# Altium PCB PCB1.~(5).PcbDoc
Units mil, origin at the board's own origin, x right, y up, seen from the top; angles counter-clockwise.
Board outline 1968 x 1968 mil, 4 copper layers (Top Layer, Internal Plane 1, Internal Plane 2, Bottom Layer), stack 18.2 mil thick; 12 components, 11 nets, 37 pads, 0 vias.
Unrouted connection lines stored in the file: 1.
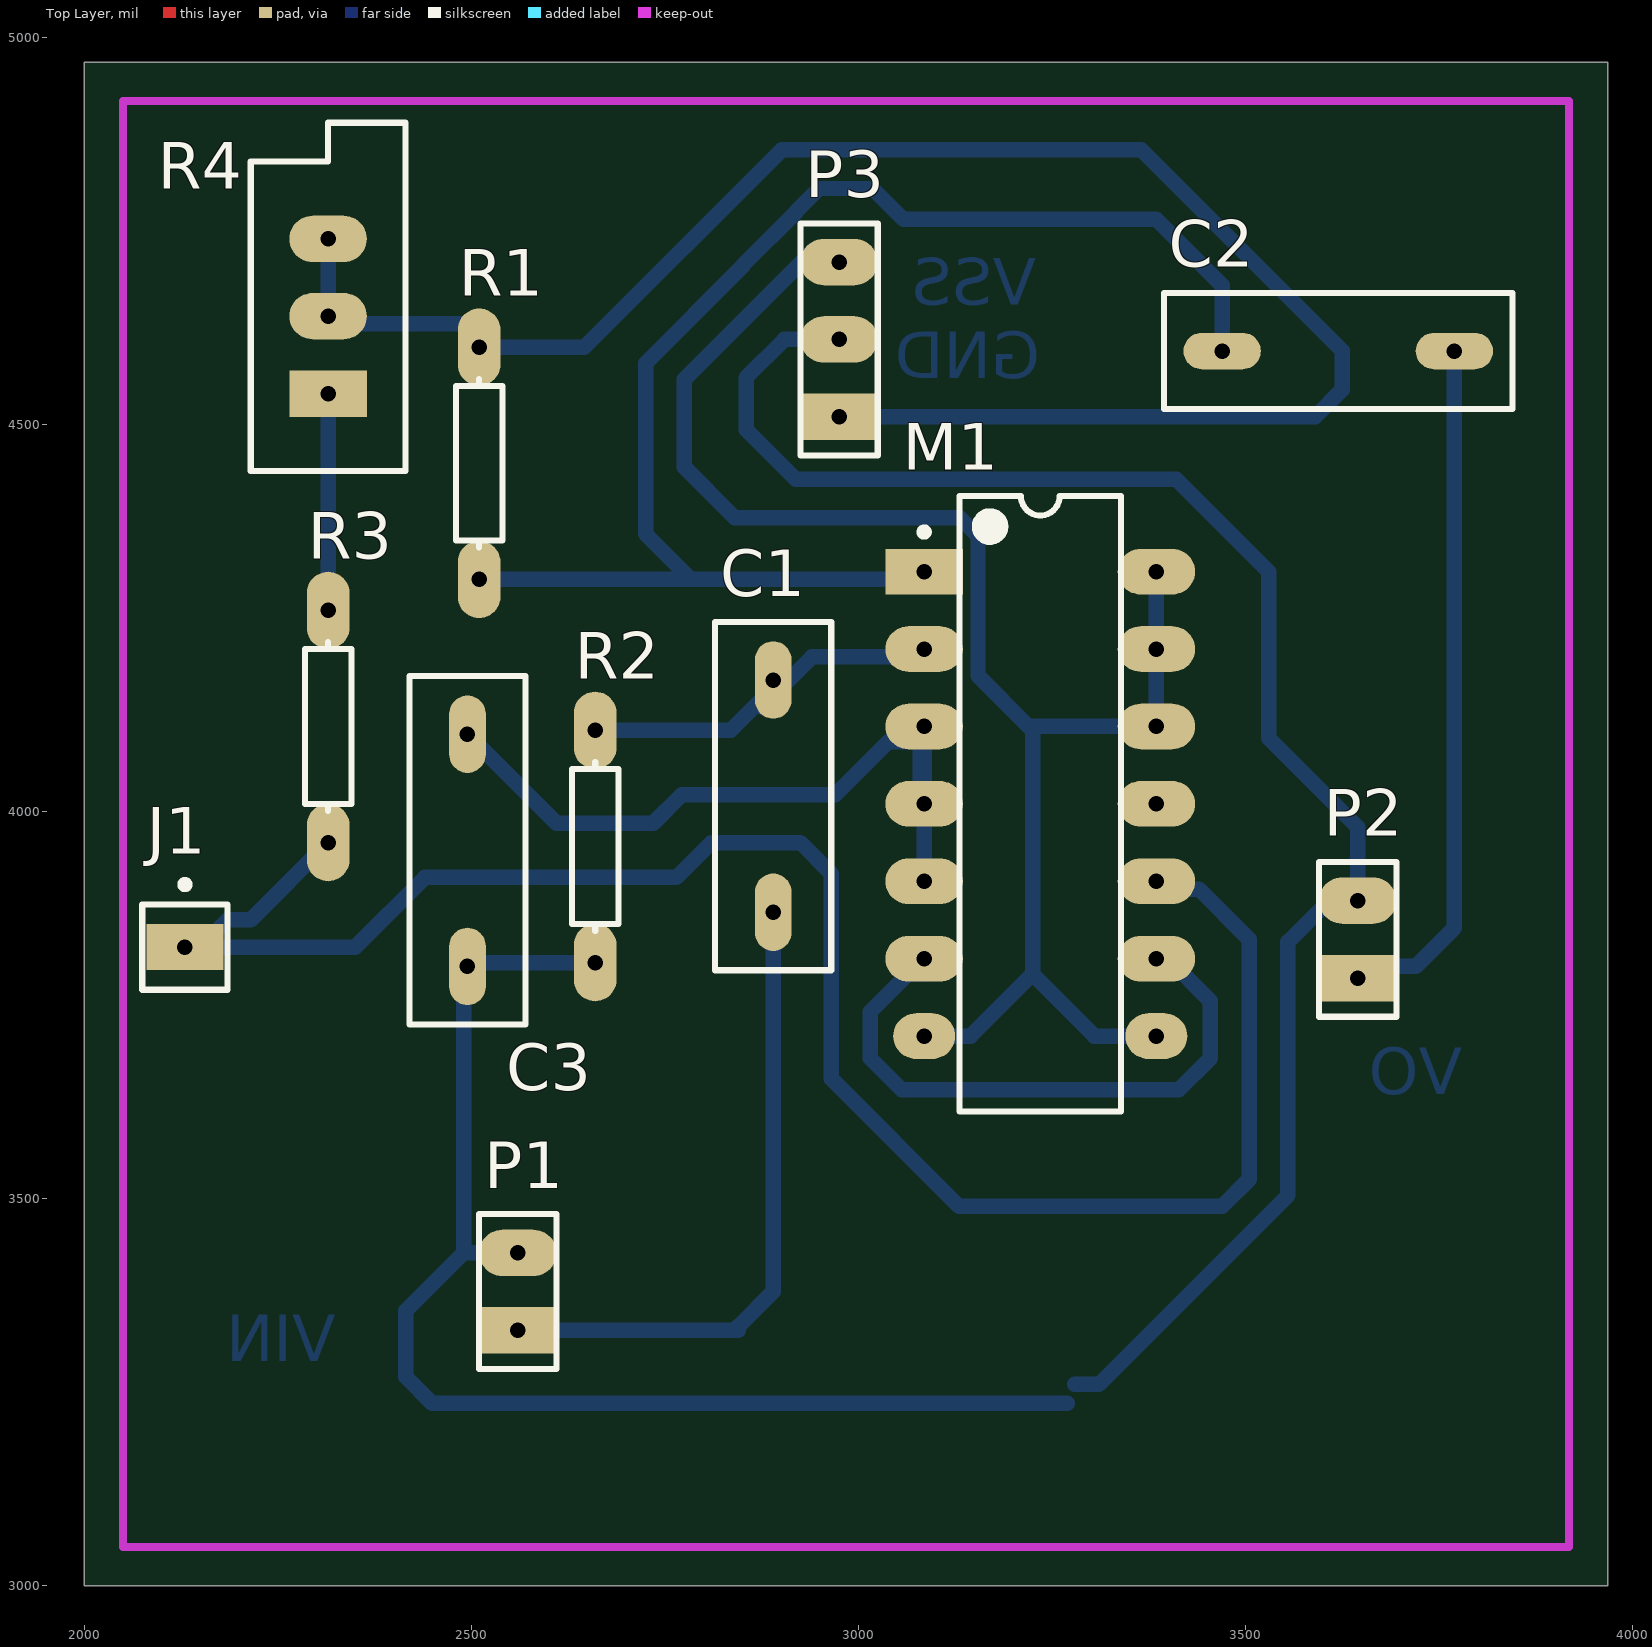
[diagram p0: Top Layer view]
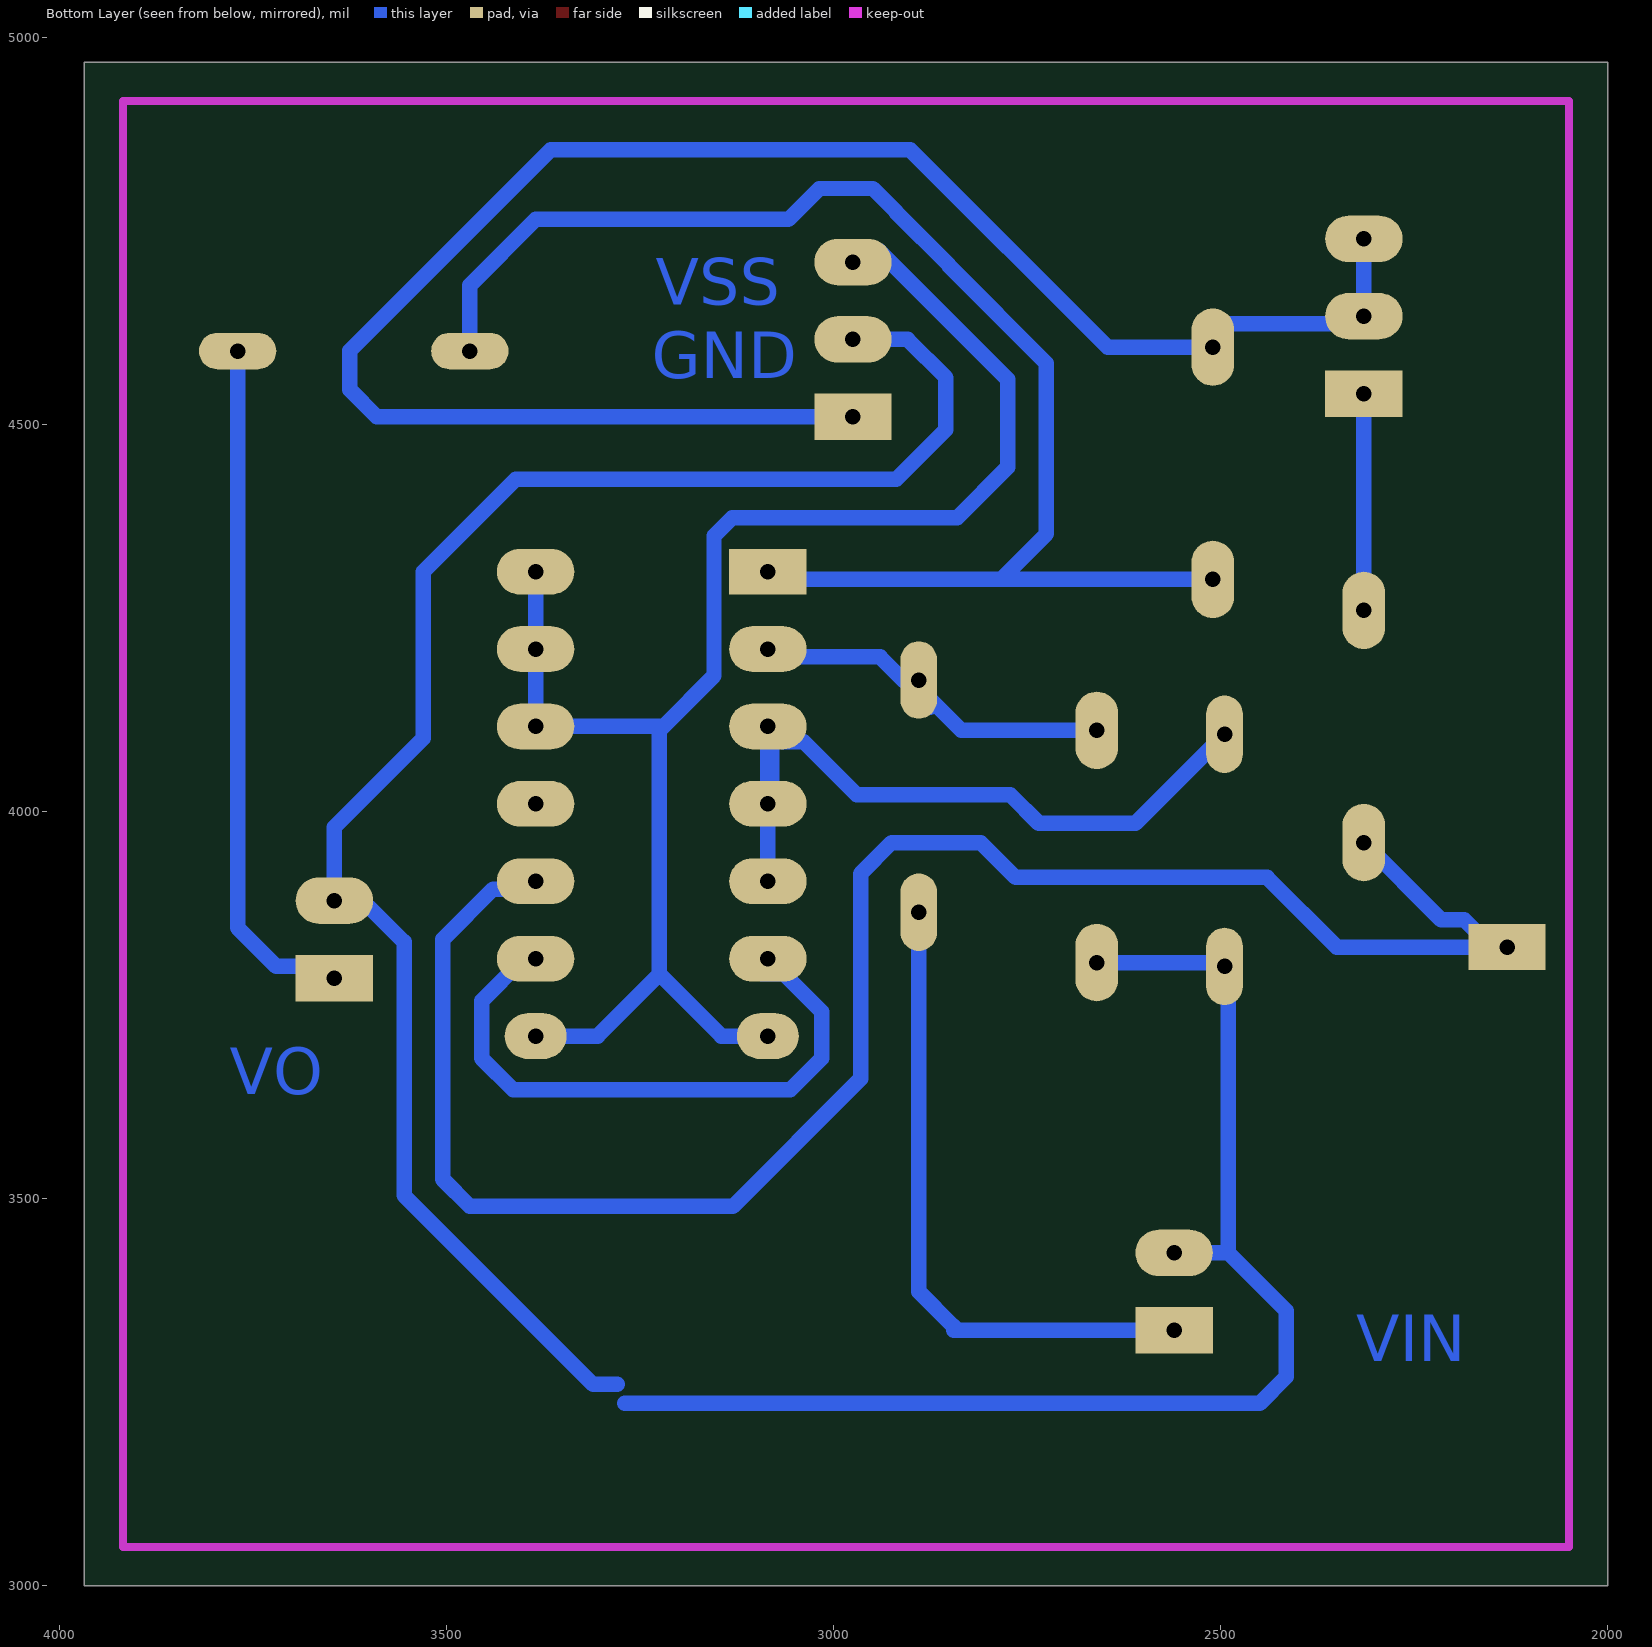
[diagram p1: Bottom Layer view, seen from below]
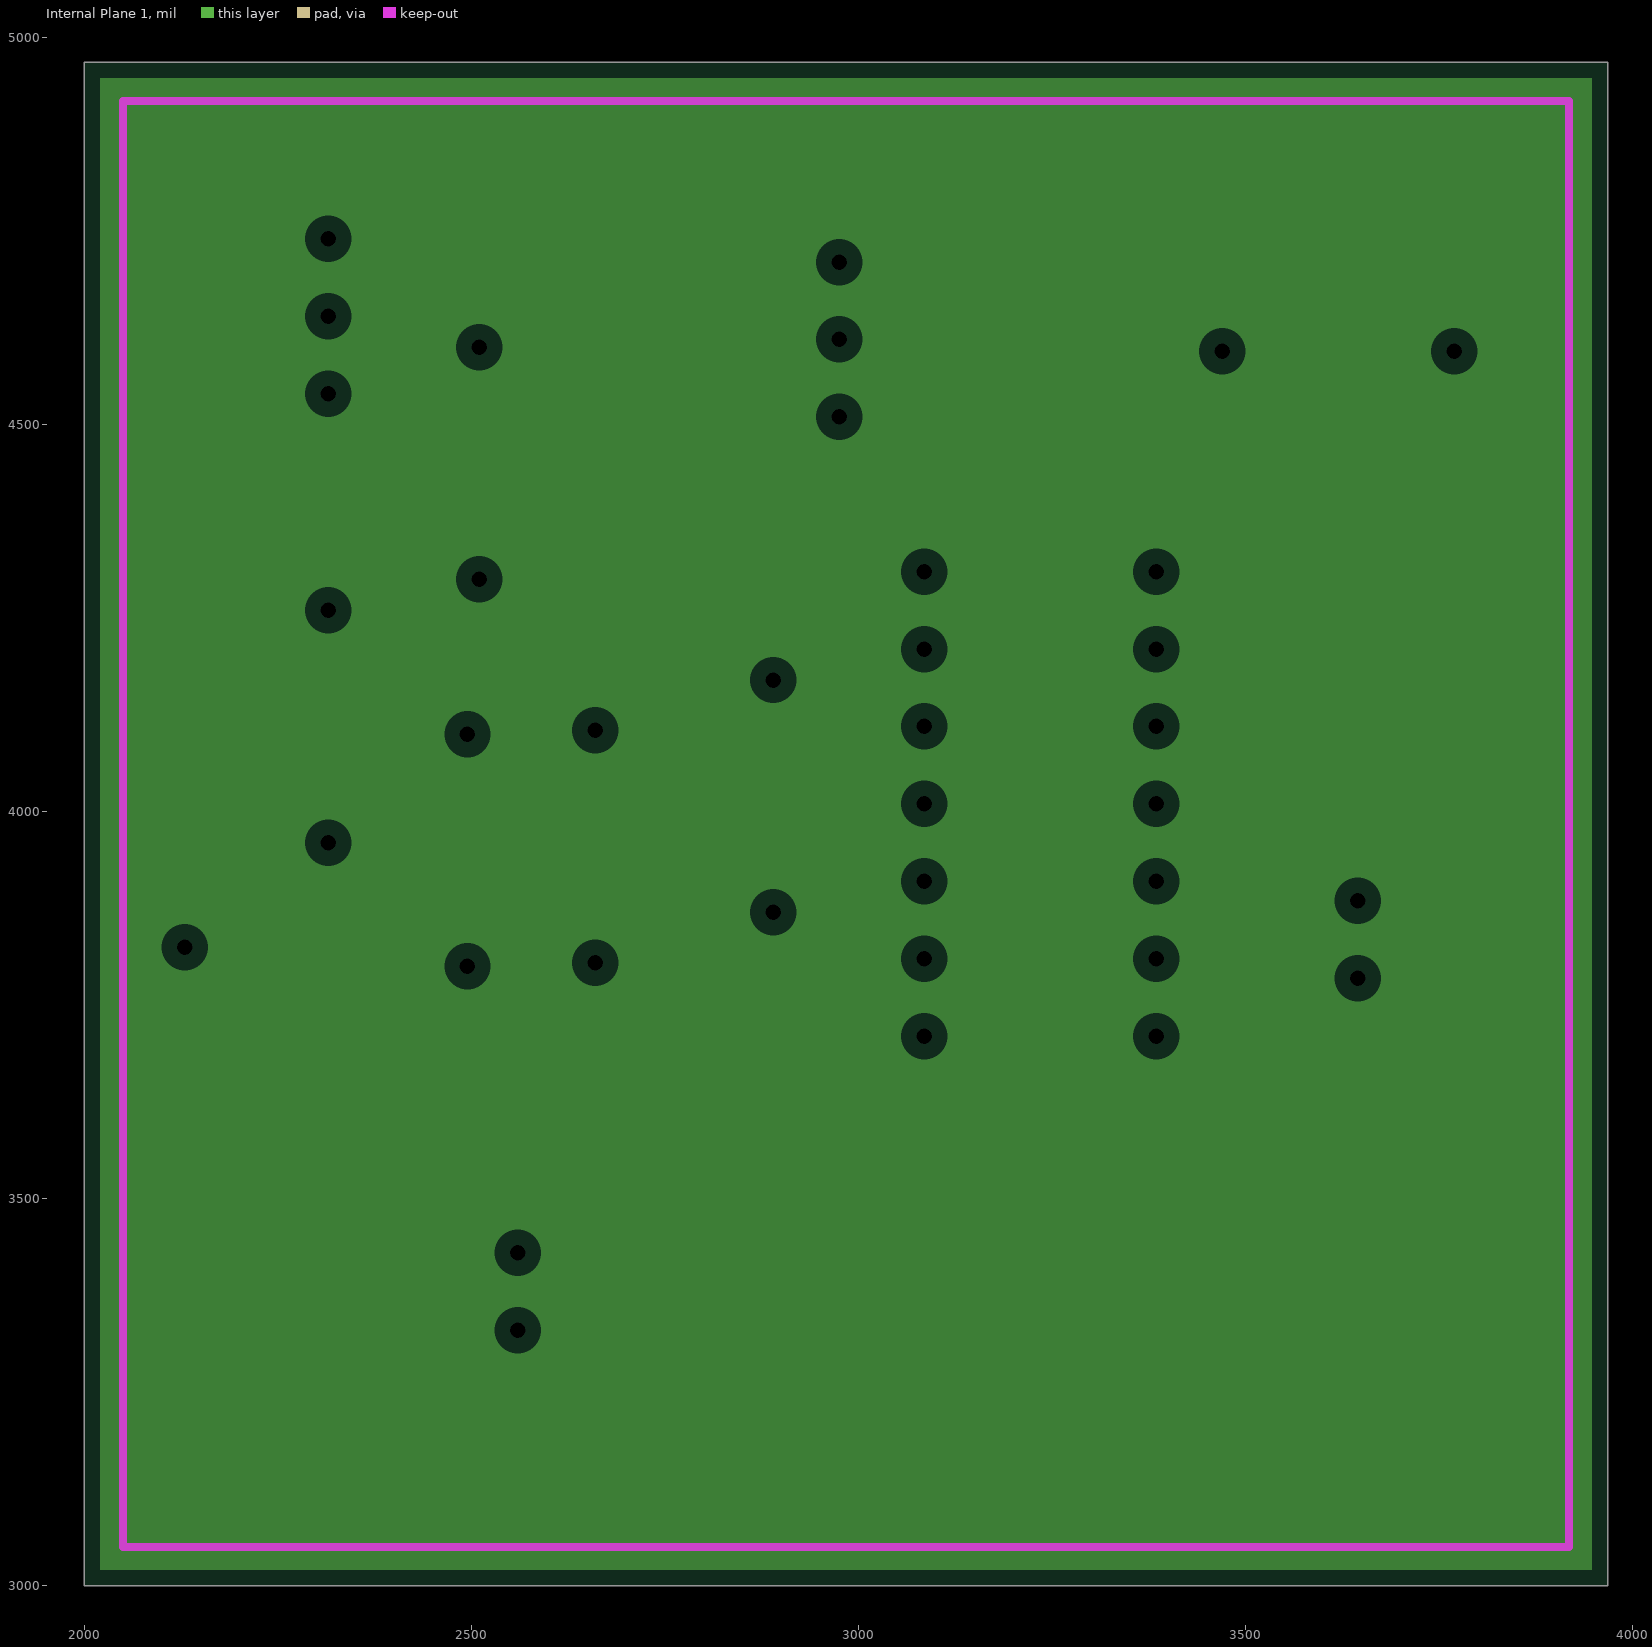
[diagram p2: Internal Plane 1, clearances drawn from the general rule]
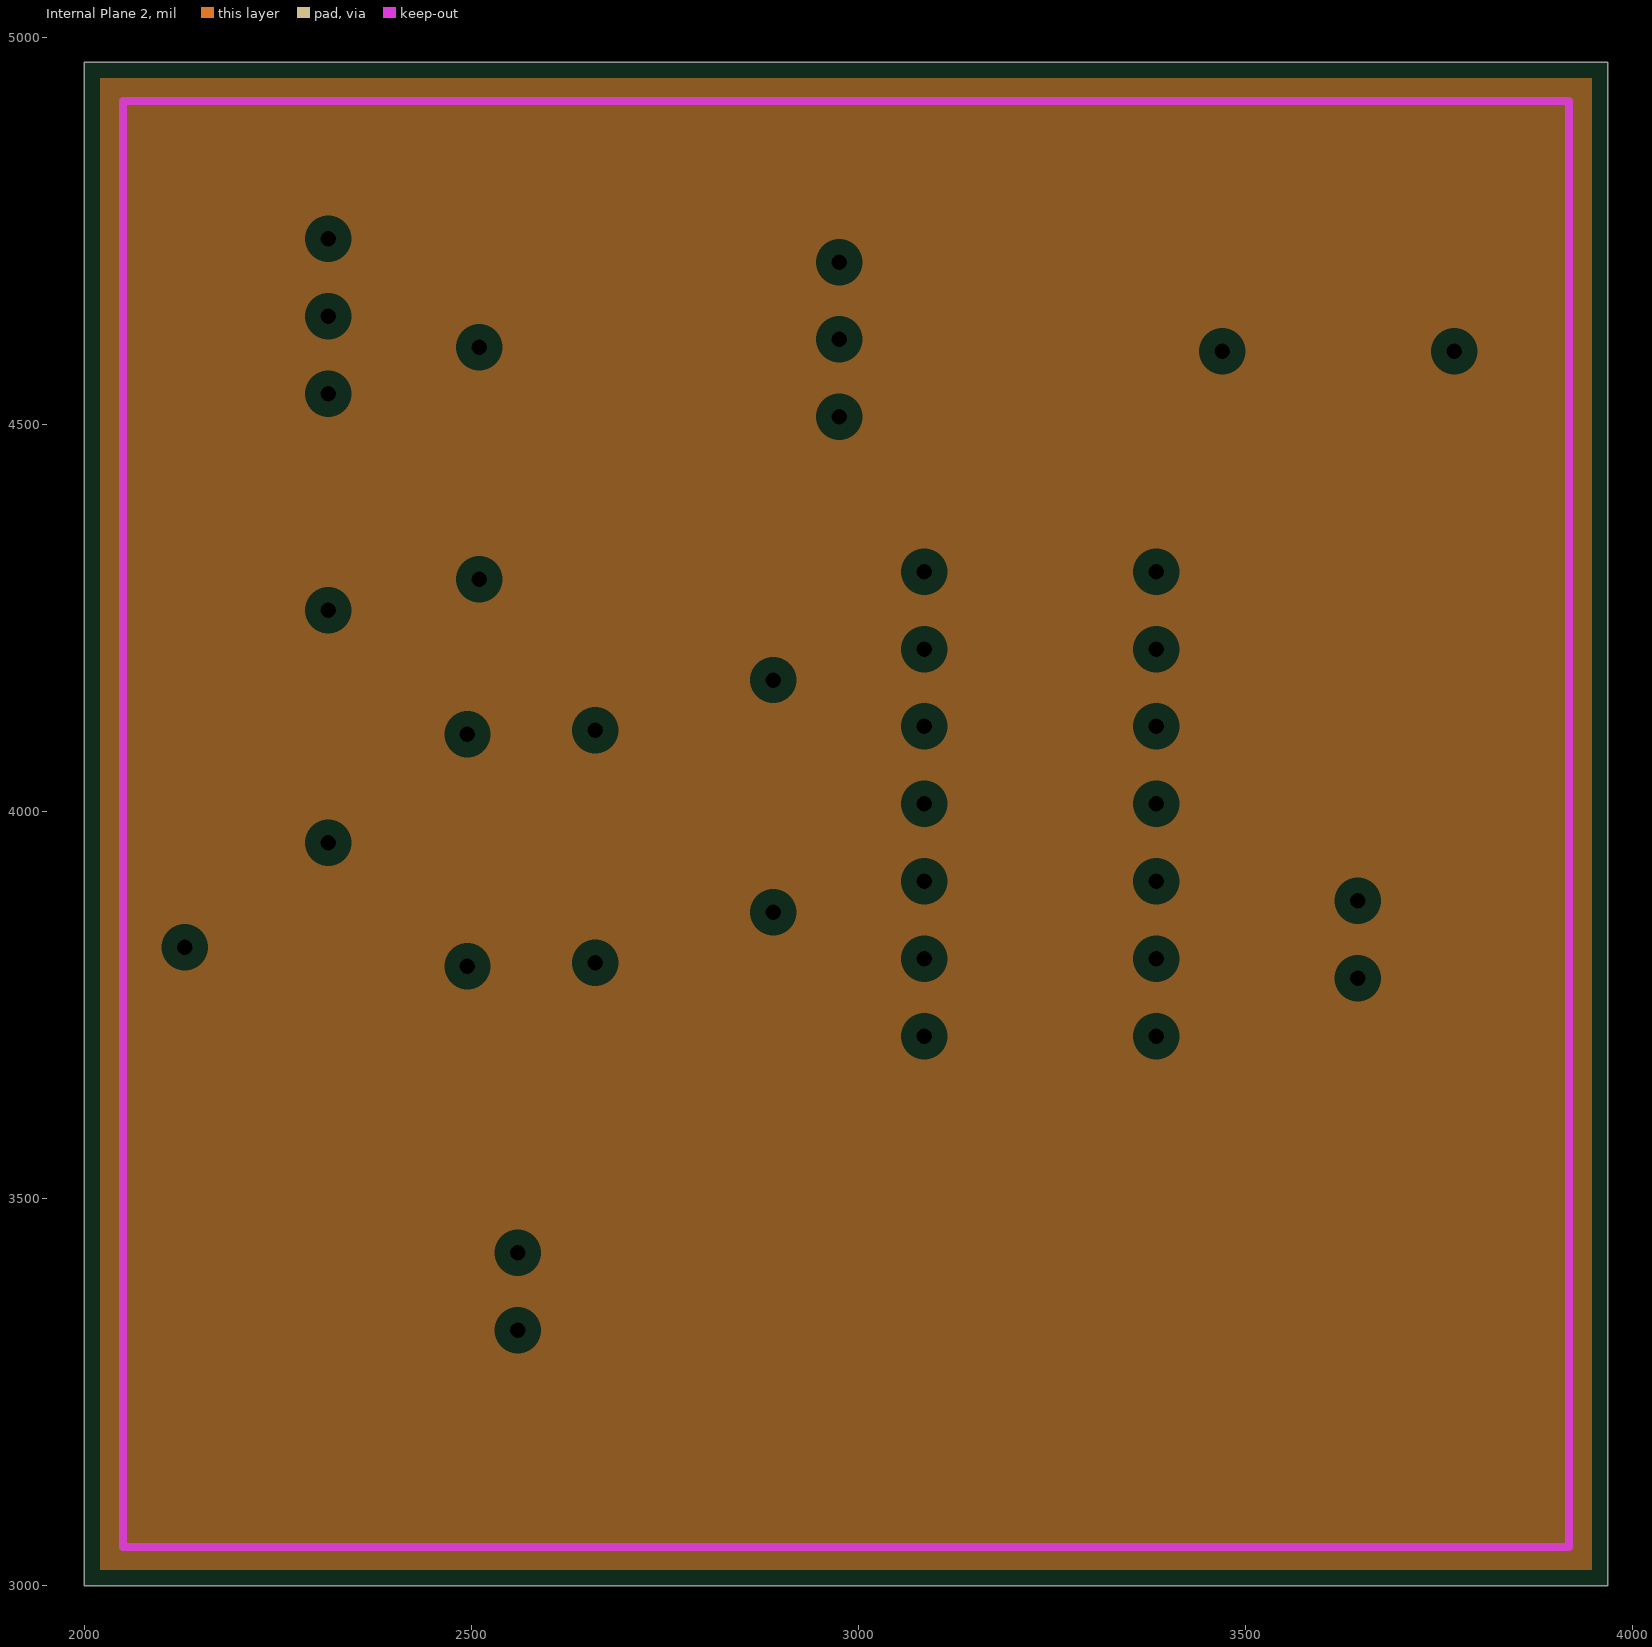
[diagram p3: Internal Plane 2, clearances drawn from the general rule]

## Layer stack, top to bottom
Top Solder: solder mask 0.4, Solder Resist, Dk 3.5
Top Layer: signal copper 1.4
Internal Plane 1: plane copper 1.4
Internal Plane 2: plane copper 1.4
Dielectric 1: dielectric 12.6, FR-4, Dk 4.8
Bottom Layer: signal copper 1.4
Bottom Solder: solder mask 0.4, Solder Resist, Dk 3.5

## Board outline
2000,3000 3968,3000 3968,4968 2000,4968

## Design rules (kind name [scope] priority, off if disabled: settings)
Clearance [All] p1: gap=30
PlaneClearance [All] p1: clearance=20
PlaneConnect [All] p1: planeconnectstyle=Relief reliefexpansion=20 reliefentries=4 reliefconductorwidth=10 reliefairgap=10
PolygonConnect [All] p1: connectstyle=Relief reliefconductorwidth=10 reliefentries=4 polygonreliefangle="90 Angle" airgapwidth=10
RoutingVias [All] p1: holewidth=32 width=62 viastyle="Through Hole" minholewidth=28 minwidth=50 maxholewidth=28 maxwidth=50
SolderMaskExpansion [All] p1: expansion=4
Width [All] p1: maxlimit=20 minlimit=20 preferedwidth=20
28 further rules are at their usual default settings.

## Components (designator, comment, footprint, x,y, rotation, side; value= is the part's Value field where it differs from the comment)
C1 "Cap" RAD-0.3 2890,4020 r90 top
C2 "Cap" RAD-0.3 3620,4595 r0 top
C3 "Cap" RAD-0.3 2495,3950 r90 top
J1 "Socket" PIN1 2130,3825 r0 top
M1 "ALD1106" DIP-14 3235,4010 r0 top
P1 "Header 2" HDR1X2 2560,3330 r90 top
P2 "Header 2" HDR1X2 3645,3785 r90 top
P3 "Header 3" HDR1X3 2975,4510 r90 top
R1 "Res1" AXIAL-0.3 2510,4450 r90 top
R2 "Res1" AXIAL-0.3 2660,3955 r90 top
R3 "Res1" AXIAL-0.3 2315,4110 r90 top
R4 "RPot" VR5 2315,4640 r90 top

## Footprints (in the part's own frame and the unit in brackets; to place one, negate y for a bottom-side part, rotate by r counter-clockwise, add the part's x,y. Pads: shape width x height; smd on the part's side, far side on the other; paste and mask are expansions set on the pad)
AXIAL-0.3 [mil] "Axial Device, Thru-Hole; 2 Leads; 0.3 in Pin Spacing"
  oval 100x55.12 hole 20: 1(-150,0) 2(150,0)
  silkscreen extent -109,-30 109,30
DIP-14 [mil] "DIP, 14-Pin, Row Spacing 7.62 mm, Pitch 2.54 mm"
  rect 100x59.06 hole 20: 1(-150,300)
  oval 100x59.06 hole 20: 2(-150,200) 3(-150,100) 4(-150,0) 5(-150,-100) 6(-150,-200) 9(150,-200) 10(150,-100) 11(150,0) 12(150,100) 13(150,200) 14(150,300)
  oval 80x59.06 hole 20: 7(-150,-300) 8(150,-300)
  silkscreen extent -155,-398 104,398, body extent -142,-398 142,398, height 200
HDR1X2 [mil] "Connector; Header; 2 Position"
  rect 60x100 hole 20: 1(0,0)
  oval 60x100 hole 20: 2(100,0)
  silkscreen extent -50,-50 150,50
HDR1X3 [mil] "Connector; Header; 3 Position"
  rect 60x100 hole 20: 1(0,0)
  oval 60x100 hole 20: 2(100,0) 3(200,0)
  silkscreen extent -50,-50 250,50
PIN1 [mil] "Connector; Plug"
  rect 100x59.06 hole 20: 1(0,0)
  silkscreen extent -55,-55 55,86
RAD-0.3 [mil] "Radial Cap, Thru-Hole; 2 Leads; 0.3 in Pin Spacing"
  oval 100x47.24 hole 20: 1(-150,0) 2(150,0)
  silkscreen extent -225,-75 225,75
VR5 [mil] "Thru-Hole; 3 Leads"
  rect 60x100 hole 20: 1(-100,0)
  oval 60x100 hole 20: 2(0,0) 3(100,0)
  silkscreen extent -200,-100 250,100

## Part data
C1 C2 C3: "Capacitor"
M1: "Quad N-channel matched MOSFET array"
P1 P2: "Header, 2-Pin"
P3: "Header, 3-Pin"
R1 R2 R3: "Resistor"
R4: "Potentiometer"

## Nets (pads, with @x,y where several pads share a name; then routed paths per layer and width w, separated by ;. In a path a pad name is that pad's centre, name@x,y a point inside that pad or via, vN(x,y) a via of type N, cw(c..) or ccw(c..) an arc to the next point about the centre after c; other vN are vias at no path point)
GND: C3.1 P1.2 P2.2 P3.2 R2.1 | length 3823.6
  Bottom Layer w20: C3.1 2490,3800 2490,3430 ; C3.1@2500,3805 R2.1@2635.71,3805 ; P1.2 2490,3430 ; P3.2@2944.53,4610 2904.29,4610 2855,4560.71 2855,4493.43 2918.9,4429.53 3410.47,4429.53 3530,4310 3530,4095 3645,3980 P2.2 P2.2@3630,3885 ; 3269.76,3235.47 2449.53,3235.47 2415,3270 2415,3355 2490,3430 ; 3279.29,3260 3310.71,3260 3555,3504.29 3555,3831.57 P2.2@3599.38,3875.94
NetC1_1: C1.1 P1.1 | length 838.6
  Bottom Layer w20: P1.1 2845,3330 ; 2845,3335 2890,3380 C1.1
NetC1_2: C1.2 M1.2 R2.2 | length 467.6
  Bottom Layer w20: R2.2 2740,4105 ; 2745,4105 2835,4105 C1.2@2875,4145 ; C1.2@2875,4135 2940,4200 3075,4200 M1.2
NetC2_1: C2.1 M1.1 R1.1 | length 1873.9
  Bottom Layer w20: R1.1 3075,4300 M1.1 ; 2783.82,4300 2725,4358.82 2725,4579.04 2850.47,4704.51 2850.47,4705.47 2920,4775 2920,4775.71 2949.29,4805 3018.33,4805 3058.33,4765 3385,4765 3470,4680 C2.1 ; 2835,4300 2850,4300
NetC2_2: C2.2 P2.1 | length 905.3
  Bottom Layer w20: P2.1 3645,3800 3720,3800 3770,3850 3770,4314.55 ; 3770,4315 C2.2
NetC3_2: C3.2 M1.3 M1.4 M1.5 | length 986.5
  Bottom Layer w20: C3.2 2610,3985 2735,3985 2771.61,4021.61 2970,4021.61 3038.86,4090.47 3065.47,4090.47 M1.3@3080,4105 ; M1.5 M1.4 ; M1.3@3080,4105 3080,4015 M1.4 ; M1.3@3080,4105 M1.3 M1.4
NetJ1_1: J1.1 M1.10 R3.1 | length 2483.2
  Bottom Layer w20: J1.1 J1.1@2150,3825 ; R3.1 2215,3860 2185,3860 J1.1@2150,3825 ; M1.10 3385,3900 3440,3900 3505,3835 3505,3525 3470,3490 3130,3490 2965,3655 2964.98,3885 2965,3920 2925,3960 2810,3960 2765,3915 2440,3915 2350,3825 J1.1@2150,3825
NetM1_4: M1.7 M1.8 M1.12 M1.13 M1.14 P3.3 | length 2120.1
  Bottom Layer w20: P3.3@2970,4724.53 2941.2,4724.53 2775,4558.33 2775,4445 2840.47,4379.53 3131.1,4379.53 3154.53,4356.1 3154.53,4175.47 3220,4110 ; M1.7 3145,3710 3225,3790 ; M1.8 3305,3710 3225,3790 ; M1.14 M1.13 M1.12 3220,4110 ; 3220,4110 3225,4105 3225,3790
NetM1_6: M1.6 M1.9 | length 822.7
  Bottom Layer w20: M1.6 3104.53,3810 3104.53,3801.91 3093.09,3790.47 3064.29,3790.47 3015.47,3741.66 3015.47,3681.2 3056.2,3640.47 3413.8,3640.47 3454.53,3681.2 3454.53,3755.47 M1.9@3402.5,3807.5
NetP3_1: P3.1 R1.2 R4.2 R4.3 | length 2360.7
  Bottom Layer w20: R4.3 R4.2 2318.81,4640 2328.81,4630 2490,4630 2510,4610 R1.2 2645.96,4600 2900.96,4855 3365.71,4855 3625,4595.71 3625,4545 3590,4510 P3.1
NetR3_2: R3.2 R4.1 | length 270
  Bottom Layer w20: R3.2@2315,4270 R4.1
pads on no net: M1.11

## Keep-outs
Keep-Out Layer:
  lines w10: 2050,3050 3918,3050 3918,4918 2050,4918 2050,3050

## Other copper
Bottom Layer:
  text "VSS" at 3230,4655 h60
  text "GND" at 3235,4560 h60
  text "VO" at 3780,3635 h60
  text "VIN" at 2325,3290 h60

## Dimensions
2050,3050 to 3918,3050 on Mechanical 1
2050,3050 to 2050,4918 on Mechanical 1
